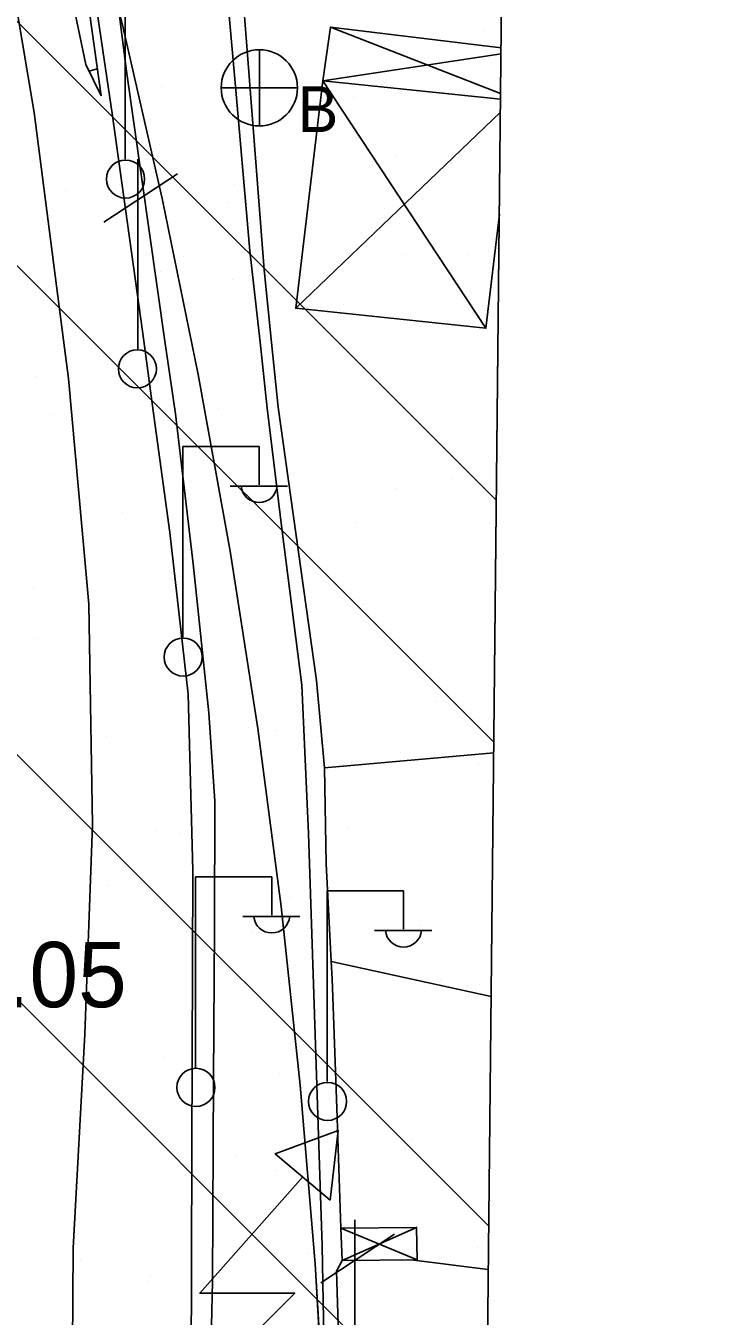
# Model space of a CAD drawing. Extents: x 417995 to 421451, y 4454518 to 4458015.
# Drawn here: x 421231.5 to 421295.4, y 4455713.8 to 4455832.3 of the extents above; entities that cross this region are included whole.
import ezdxf

# ---------------------------------------------------------------- set-up
doc = ezdxf.new("R2010")
doc.units = 0
for name, color, linetype in [('ADAKENARI', 7, 'Continuous'), ('B_Kapi', 7, 'Continuous'), ('B_Sundurma', 7, 'Continuous'), ('Default', 7, 'Continuous'), ('PAFTALAMA', 7, 'Continuous'), ('PL_AYA_BOLGE_PARKI', 7, 'Continuous'), ('PL_AYA_PARK_DINLENME', 7, 'Continuous'), ('S_Elektrik_Diregi', 7, 'Continuous'), ('S_Rogar_Kapagi_Buski', 7, 'Continuous'), ('S_Telefon_Diregi', 7, 'Continuous'), ('S_Trafo_acik_tip', 7, 'Continuous'), ('Sev_Sevalti', 7, 'Continuous'), ('Sev_Sevustu', 7, 'Continuous'), ('Sev_Tarama', 7, 'Continuous'), ('Sinir_Cit_bir_taraf', 7, 'Continuous'), ('Sinir_Tel_bir_taraf', 7, 'Continuous'), ('SN_TR_SIVILASMA', 7, 'Continuous'), ('TR_PARKALANI', 7, 'Continuous'), ('Y_Lejant', 7, 'Continuous'), ('Y_Yol_Kotu', 7, 'Continuous'), ('Yol_Sose', 7, 'Continuous')]:
    doc.layers.add(name, color=color, linetype=linetype)

# ---------------------------------------------------------------- blocks, each defined once
blk = doc.blocks.new('POINT_DISPLAY')
at = {"layer": 'Default'}
blk.add_line((0, 0), (0, 0), dxfattribs=at)

msp = doc.modelspace()

# ---------------------------------------------------------------- linework, layer by layer
at = {"layer": 'ADAKENARI'}
for p, q in [((421243.98, 4455816.42), (421240.3, 4455832.49)), ((421247.29, 4455800.26), (421243.98, 4455816.42)), ((421250.21, 4455784.03), (421247.29, 4455800.26)), ((421252.74, 4455767.74), (421250.21, 4455784.03)), ((421254.89, 4455751.39), (421252.74, 4455767.74)), ((421256.64, 4455734.99), (421254.89, 4455751.39)), ((421258.01, 4455718.56), (421256.64, 4455734.99)), ((421258.99, 4455702.09), (421258.01, 4455718.56))]:
    msp.add_line(p, q, dxfattribs=at)
at = {"layer": 'B_Kapi'}
for points in [[(421258.86, 4455764.12), (421258.14, 4455772.14)], [(421259.47, 4455746.33), (421259.02, 4455755.3)], [(421259.99, 4455732.86), (421259.56, 4455744.75)]]:
    msp.add_lwpolyline(points, dxfattribs=at)
at = {"layer": 'B_Sundurma'}
for p, q in [((421275.03, 4455826.07), (421259.41, 4455832.16)), ((421275.07, 4455829.69), (421258.73, 4455827.21)), ((421273.68, 4455804.5), (421258.73, 4455827.21)), ((421275.01, 4455824.36), (421256.23, 4455806.33)), ((421260.38, 4455721.85), (421267.36, 4455718.94)), ((421260.48, 4455718.87), (421267.32, 4455721.92))]:
    msp.add_line(p, q, dxfattribs=at)
for points in [[(421275.07, 4455830.24), (421259.41, 4455832.16), (421258.73, 4455827.21), (421275.03, 4455825.55)], [(421275.03, 4455825.55), (421258.73, 4455827.21), (421259.41, 4455832.16), (421275.07, 4455830.24)], [(421274.92, 4455814.99), (421273.68, 4455804.5), (421256.23, 4455806.33), (421258.73, 4455827.21), (421275.03, 4455825.55)], [(421274.92, 4455814.99), (421273.68, 4455804.5), (421256.23, 4455806.33), (421258.73, 4455827.21), (421275.03, 4455825.55)]]:
    msp.add_lwpolyline(points, dxfattribs=at)
for points in [[(421260.38, 4455721.85), (421260.48, 4455718.87), (421267.36, 4455718.94), (421267.32, 4455721.92)], [(421260.38, 4455721.85), (421267.32, 4455721.92), (421267.36, 4455718.94), (421260.48, 4455718.87)]]:
    msp.add_lwpolyline(points, close=True, dxfattribs=at)
at = {"layer": 'PAFTALAMA'}
msp.add_line((421266.41, 4454999.4), (421295.36, 4457775.52), dxfattribs=at)
at = {"layer": 'PL_AYA_BOLGE_PARKI'}
msp.add_line((421271.52, 4455489.32), (421283.96, 4456682.26), dxfattribs=at)
msp.add_lwpolyline([(421216.89, 4455920.89), (421236.23, 4455848.47), (421240.3, 4455832.49), (421243.98, 4455816.42), (421247.29, 4455800.26), (421250.21, 4455784.03), (421252.74, 4455767.74), (421254.89, 4455751.39), (421256.64, 4455734.99), (421258.01, 4455718.56), (421258.99, 4455702.09), (421259.58, 4455685.61), (421259.77, 4455669.13), (421259.58, 4455652.64), (421258.99, 4455636.16), (421258.01, 4455619.7), (421256.64, 4455603.26), (421254.88, 4455586.87), (421252.74, 4455570.52), (421250.21, 4455554.22), (421247.29, 4455537.99), (421243.98, 4455521.84), (421240.3, 4455505.76), (421271.52, 4455489.32)], dxfattribs=at)
at = {"layer": 'PL_AYA_PARK_DINLENME'}
msp.add_lwpolyline([(421188.93, 4456006.25), (421195.28, 4455989.43), (421201.25, 4455972.48), (421206.84, 4455955.4), (421212.06, 4455938.2), (421216.89, 4455920.89), (421236.23, 4455848.47), (421240.3, 4455832.49), (421243.98, 4455816.42), (421247.29, 4455800.26), (421250.21, 4455784.03), (421252.74, 4455767.74), (421254.89, 4455751.39), (421256.64, 4455734.99), (421258.01, 4455718.56), (421258.99, 4455702.09)], dxfattribs=at)
at = {"layer": 'S_Elektrik_Diregi'}
for p, q in [((421240.57, 4455820.04), (421240.57, 4455837.54)), ((421245.87, 4455776.13), (421245.87, 4455793.63)), ((421245.87, 4455793.63), (421252.87, 4455793.63)), ((421252.87, 4455790.13), (421252.87, 4455793.63)), ((421250.21, 4455789.99), (421255.46, 4455789.99)), ((421247.03, 4455736.61), (421247.03, 4455754.11)), ((421247.03, 4455754.11), (421254.03, 4455754.11)), ((421254.03, 4455750.61), (421254.03, 4455754.11)), ((421259.12, 4455735.32), (421259.12, 4455752.82)), ((421259.12, 4455752.82), (421266.12, 4455752.82)), ((421266.12, 4455749.32), (421266.12, 4455752.82)), ((421251.37, 4455750.47), (421256.62, 4455750.47)), ((421263.46, 4455749.18), (421268.71, 4455749.18))]:
    msp.add_line(p, q, dxfattribs=at)
for centre in [(421240.61, 4455818.2), (421245.9, 4455774.3), (421247.07, 4455734.78), (421259.15, 4455733.49)]:
    msp.add_circle(centre, 1.75, dxfattribs=at)
for centre in [(421252.87, 4455790.15), (421254.03, 4455750.62), (421266.12, 4455749.33)]:
    msp.add_arc(centre, 1.66, 184.8384, 355.1464, dxfattribs=at)
at = {"layer": 'S_Rogar_Kapagi_Buski'}
for p, q in [((421252.89, 4455830.08), (421252.89, 4455823.08)), ((421249.39, 4455826.58), (421256.39, 4455826.58))]:
    msp.add_line(p, q, dxfattribs=at)
msp.add_circle((421252.89, 4455826.58), 3.5, dxfattribs=at)
at = {"layer": 'S_Telefon_Diregi'}
for p, q in [((421241.74, 4455802.52), (421241.74, 4455820.02)), ((421238.62, 4455814.24), (421245.38, 4455818.69)), ((421261.65, 4455705.11), (421261.65, 4455722.62)), ((421258.53, 4455716.84), (421265.29, 4455721.29))]:
    msp.add_line(p, q, dxfattribs=at)
msp.add_circle((421241.7, 4455800.77), 1.75, dxfattribs=at)
at = {"layer": 'S_Trafo_acik_tip'}
msp.add_lwpolyline([(421259.39, 4455724.42), (421260.13, 4455730.83), (421254.35, 4455728.69)], close=True, dxfattribs=at)
msp.add_lwpolyline([(421246.48, 4455706.22), (421256.14, 4455715.88), (421247.42, 4455715.88), (421256.87, 4455726.56)], dxfattribs=at)
at = {"layer": 'Sev_Sevalti'}
msp.add_lwpolyline([(421238.37, 4455825.84), (421236.91, 4455836.38), (421235.56, 4455844.34), (421234.48, 4455852.03), (421233.96, 4455857.81), (421233.49, 4455864.36), (421233.36, 4455871.37), (421232.97, 4455878.32), (421232.72, 4455885.47), (421232.69, 4455888.92), (421233.12, 4455893.26), (421234.6, 4455902.15), (421235.06, 4455909.06), (421235.96, 4455915.99), (421236.98, 4455926.81), (421238.14, 4455938.54), (421239.02, 4455946.57), (421240.5, 4455958.95), (421241.37, 4455965.94), (421242.06, 4455973.12), (421242.88, 4455980.36), (421244.09, 4455987.73), (421246.22, 4455999.35), (421248, 4456005.73)], dxfattribs=at)
at = {"layer": 'Sev_Sevustu'}
msp.add_lwpolyline([(421238.37, 4455825.84), (421236.97, 4455828.73), (421234.3, 4455841.48), (421231.77, 4455853.73), (421230.69, 4455867.57), (421229.99, 4455879.64), (421228.88, 4455890.14), (421228.71, 4455890.36), (421230.91, 4455902.6), (421231.9, 4455914), (421233.36, 4455927.7), (421234.51, 4455941.48), (421235.38, 4455954.35), (421235.93, 4455965.18), (421237.24, 4455980.84), (421239.21, 4455995.42), (421240.31, 4456003.18)], dxfattribs=at)
at = {"layer": 'Sev_Tarama'}
msp.add_line((421237.28, 4455828.1), (421238.02, 4455828.34), dxfattribs=at)
at = {"layer": 'Sinir_Cit_bir_taraf'}
for points in [[(421259.56, 4455744.75), (421259.47, 4455746.33), (421274.17, 4455743.13)], [(421260.38, 4455721.85), (421259.99, 4455732.86)], [(421273.9, 4455718.06), (421266.83, 4455718.94)]]:
    msp.add_lwpolyline(points, dxfattribs=at)
at = {"layer": 'Sinir_Tel_bir_taraf'}
for points in [[(421247.6, 4456002.64), (421245.99, 4455991.43), (421244.66, 4455980.97), (421243.14, 4455969.99), (421241.9, 4455960.52), (421240.42, 4455949.76), (421239.26, 4455939.32), (421237.96, 4455926.26), (421236.82, 4455914.03), (421235.69, 4455903.18), (421235.01, 4455896.66), (421234.25, 4455889.86), (421234.33, 4455879.41), (421234.45, 4455869.67), (421234.91, 4455859.26), (421236.21, 4455846.87), (421237.65, 4455836.05), (421239.38, 4455824.21), (421241.86, 4455806.44), (421242.28, 4455803.33)], [(421254.01, 4455803.2), (421253.34, 4455809.87), (421251.74, 4455830.4), (421251, 4455839.84), (421257.45, 4455838.98), (421269.62, 4455836.78), (421275.11, 4455833.55)], [(421242.28, 4455803.33), (421243.16, 4455796.9)], [(421254.62, 4455797.25), (421254.01, 4455803.2)], [(421246.42, 4455695.73), (421246.62, 4455708.75), (421246.69, 4455729.02), (421246.79, 4455754.71), (421246.35, 4455770.88), (421244.69, 4455785.73), (421243.16, 4455796.9)], [(421258.14, 4455772.14), (421254.62, 4455797.25)], [(421274.4, 4455765.51), (421258.86, 4455764.12)], [(421259.02, 4455755.3), (421258.86, 4455764.12)], [(421260.65, 4455696.44), (421259.98, 4455717.89), (421260.48, 4455718.87)]]:
    msp.add_lwpolyline(points, dxfattribs=at)
at = {"layer": 'SN_TR_SIVILASMA'}
for p, q in [((421274.64, 4455788.69), (420075.79, 4456987.53)), ((421274.41, 4455766.47), (420135.66, 4456905.22)), ((421273.94, 4455722.03), (420248.84, 4456747.14)), ((421273.71, 4455699.81), (420266.8, 4456706.72))]:
    msp.add_line(p, q, dxfattribs=at)
at = {"layer": 'Y_Lejant'}
msp.add_lwpolyline([(419168.18, 4457798.01), (421295.36, 4457775.52), (421266.41, 4454999.4), (419138.44, 4455021.89)], close=True, dxfattribs=at)
at = {"layer": 'Yol_Sose'}
for points in [[(421234.93, 4455803.4), (421232.22, 4455824.32), (421228.39, 4455846.9), (421225.17, 4455867.38), (421221.19, 4455890.26), (421218.45, 4455907.65), (421215.94, 4455923.64), (421213.41, 4455941.61), (421210.22, 4455962.6), (421207.37, 4455982.29), (421204.74, 4456002.58), (421201.7, 4456024.53), (421198.54, 4456047.92), (421196.17, 4456066.84), (421194.09, 4456082.19), (421189.82, 4456108.77)], [(421252.67, 4456025.65), (421248.93, 4455996.36), (421245.44, 4455970.97), (421242.31, 4455944.84), (421239.58, 4455922.06), (421236.75, 4455895.62), (421236.15, 4455888.34), (421236.87, 4455863.82), (421237.47, 4455853.63), (421240.69, 4455828.11), (421244.23, 4455803.3)], [(421252.95, 4455803.21), (421252.03, 4455811.61), (421250.72, 4455826.36), (421249.48, 4455840.43), (421248.24, 4455853.48), (421246.61, 4455872.36), (421245.75, 4455883.91), (421245.36, 4455890.55), (421245.43, 4455896.12), (421246.31, 4455907.75), (421248.79, 4455928.8), (421248.89, 4455929.08), (421249.08, 4455929.23), (421250.04, 4455929.23)], [(421235.39, 4455799.88), (421234.93, 4455803.4)], [(421244.23, 4455803.3), (421245.18, 4455796.64)], [(421253.62, 4455797.15), (421252.95, 4455803.21)], [(421235.39, 4455799.88), (421237.25, 4455779.16), (421237.57, 4455758.88), (421236.89, 4455739.68), (421235.8, 4455720.02), (421235.67, 4455701.95)], [(421245.18, 4455796.64), (421246.81, 4455782.87), (421248.25, 4455769.17), (421248.79, 4455761.06), (421248.78, 4455749.39), (421248.69, 4455735.6), (421248.6, 4455716.97), (421248.13, 4455696.46), (421247.83, 4455695.93), (421246.42, 4455695.73)], [(421261.2, 4455696.02), (421259.77, 4455697.12), (421259.05, 4455698.31), (421258.64, 4455720.23), (421257.41, 4455758.1), (421256.78, 4455771.72), (421254.94, 4455786.1), (421253.62, 4455797.15)]]:
    msp.add_lwpolyline(points, dxfattribs=at)

# ---------------------------------------------------------------- block references
at = {"layer": 'TR_PARKALANI', "xscale": 0.1, "yscale": 0.10000000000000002}
for p in [(421273.48, 4455831.87), (421258.71, 4455829.26), (421243.94, 4455826.66), (421268.65, 4455826.08), (421239.95, 4455824.99), (421261.56, 4455825.65), (421265.37, 4455820.29), (421250.6, 4455817.68), (421235.13, 4455817.15), (421250.07, 4455816.01), (421266.05, 4455811.31), (421272.03, 4455811.31), (421243.84, 4455809.68), (421241.79, 4455808.17), (421250.41, 4455808.99), (421257.26, 4455808.7), (421232.35, 4455800.04), (421235.61, 4455800.37), (421263.92, 4455799.72), (421233.68, 4455796.58), (421249.14, 4455797.12), (421270.58, 4455790.74), (421265.52, 4455789.81), (421255.81, 4455788.14), (421240.34, 4455787.6), (421261.71, 4455786.69), (421232.14, 4455780.67), (421247, 4455778.62), (421262.47, 4455779.16), (421246.91, 4455778.07), (421232.23, 4455776.02), (421247.8, 4455773.85), (421269.13, 4455770.18), (421256.63, 4455769.3), (421238.89, 4455767.04), (421254.35, 4455767.57), (421258.23, 4455766.99), (421273.01, 4455764.39), (421243.44, 4455758.37), (421261.01, 4455758.59), (421245.55, 4455758.06), (421238.91, 4455753.33), (421255.63, 4455752.22), (421252.21, 4455749.08), (421267.68, 4455749.61), (421237.44, 4455746.47), (421269.53, 4455744.69), (421240.83, 4455743.6), (421272.08, 4455743.1), (421259.56, 4455738.03), (421244.1, 4455737.49), (421254.74, 4455736.07), (421260.59, 4455733.46), (421266.93, 4455729.92), (421266.22, 4455729.05), (421250.76, 4455728.51), (421254.36, 4455727.13), (421235.99, 4455725.91), (421252.13, 4455721.3), (421257.42, 4455719.53), (421272.88, 4455720.07), (421236.49, 4455718.98), (421242.65, 4455716.93), (421242.87, 4455717.49), (421258.11, 4455717.46)]:
    msp.add_blockref('POINT_DISPLAY', p, dxfattribs=at)

# ---------------------------------------------------------------- texts
at = {"layer": 'S_Rogar_Kapagi_Buski'}
msp.add_text('B', height=4.2, dxfattribs=at).set_placement((421256.39, 4455822.52))
at = {"layer": 'Y_Yol_Kotu'}
msp.add_text('92.05', height=6, dxfattribs=at).set_placement((421220.64, 4455742.14))

doc.saveas('drawing.dxf')
